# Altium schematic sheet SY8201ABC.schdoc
size 127 x 101 mm
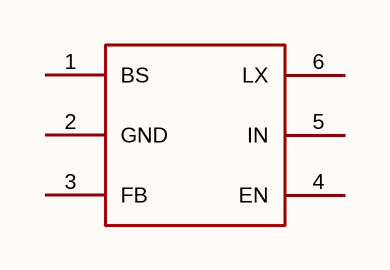
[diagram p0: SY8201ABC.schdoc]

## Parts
U?  sy8201abc  [SOT-23-6_L2.9-W1.6-P0.95-LS2.8-BR]  (value not drawn)

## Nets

Not connected (* = marked no-connect by the designer): U? 1(BS) 2(GND) 3(FB) 4(EN) 5(IN) 6(LX)

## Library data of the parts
U? = sy8201abc: 功能类型:降压型;工作电压:4.5V~27V;输出电压:-;输出电流:1A;输出类型:可调;; Manufacturer: Silergy(矽力杰); AddInBom: yes; ModelId: 18da8f6c14a34920b3e136b5c401a119; ModelName: SOT-23-6_L2.9-W1.6-H1.5-LS2.8-P0.95; ModelTransform: 110.73671,114.173,0,180,0,0,0.001,-0.003,0; Function: 降压型; Output Current: 1A; Frequency - Switching: 500kHz; Synchronous Rectifier: 是; Number of Outputs: 1; Topology: 降压式; Quiescent Current: 400uA; Switch tube (built-in/external): 内置; Output Type: 可调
